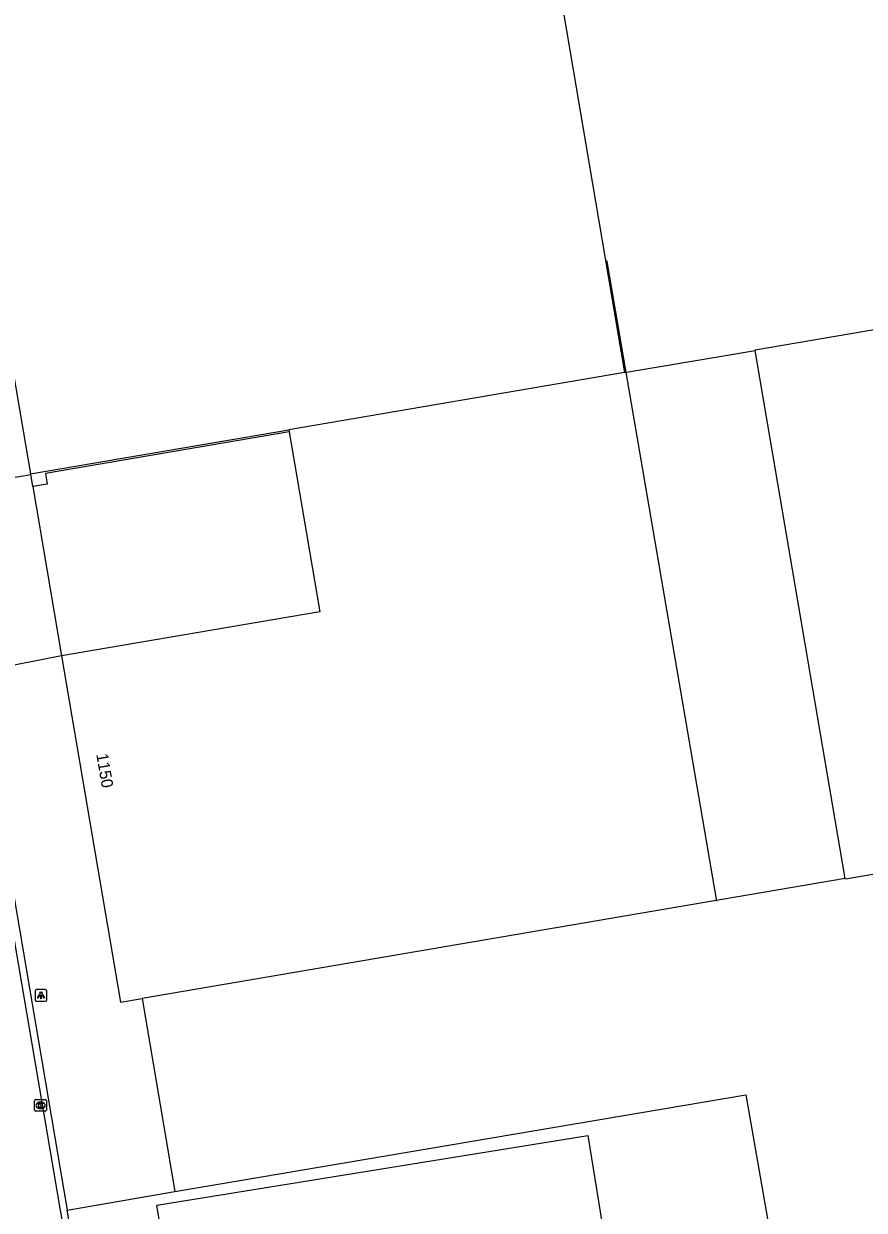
# Model space of a CAD drawing. Extents: x 154324 to 155743, y 382939 to 384183.
# Drawn here: x 154882.3 to 154954.2, y 383668.1 to 383769.7 of the extents above; entities that cross this region are included whole.
import ezdxf

# ---------------------------------------------------------------- set-up
doc = ezdxf.new("R2010")
doc.units = 0
for name, color, linetype in [('IMGEO_Grasland_agrarisch', 7, 'Continuous'), ('IMGEO_Hek', 7, 'Continuous'), ('IMGEO_Kolk', 7, 'Continuous'), ('IMGEO_Lichtpunt', 7, 'Continuous'), ('IMGEO_Muur', 7, 'Continuous'), ('IMGEO_Pand', 7, 'Continuous'), ('IMGEO_Pand_nummerreeks', 7, 'Continuous'), ('IMGEO_Pand_vergunning_verleend', 7, 'Continuous'), ('IMGEO_Rijbaan_lokaal_gesloten', 7, 'Continuous'), ('IMGEO_Rijbaan_lokaal_open', 7, 'Continuous'), ('IMGEO_Voetpad_open', 7, 'Continuous')]:
    doc.layers.add(name, color=color, linetype=linetype)

msp = doc.modelspace()

# ---------------------------------------------------------------- linework, layer by layer
at = {"layer": 'IMGEO_Grasland_agrarisch'}
msp.add_lwpolyline([(154895.23, 383669.68), (154944.1, 383677.97), (154949.34, 383647.91), (154982.71, 383457.88)], dxfattribs=at)
at = {"layer": 'IMGEO_Hek'}
msp.add_lwpolyline([(154932.18, 383749.38), (154932.22, 383749.12), (154941.57, 383694.55)], dxfattribs=at)
at = {"layer": 'IMGEO_Kolk'}
for p, q in [((154883.22, 383676.64), (154883.22, 383677.49)), ((154883.29, 383677.56), (154884.15, 383677.56)), ((154883.71, 383677.34), (154883.73, 383677.34)), ((154884.22, 383677.49), (154884.22, 383676.64)), ((154884.15, 383676.56), (154883.29, 383676.56)), ((154883.73, 383676.78), (154883.7, 383676.78))]:
    msp.add_line(p, q, dxfattribs=at)
for points in [[(154883.22, 383676.64), (154883.22, 383677.49)], [(154883.29, 383677.56), (154884.15, 383677.56)], [(154883.54, 383677.26), (154883.66, 383677.26), (154883.66, 383677.11), (154883.79, 383677.26), (154883.96, 383677.26), (154883.81, 383677.11), (154883.96, 383676.86), (154883.81, 383676.86), (154883.73, 383677.03), (154883.66, 383676.96), (154883.66, 383676.86), (154883.54, 383676.86), (154883.54, 383677.26)], [(154884.22, 383677.49), (154884.22, 383676.64)], [(154884.15, 383676.56), (154883.29, 383676.56)]]:
    msp.add_lwpolyline(points, dxfattribs=at)
for centre, start, end in [((154883.3, 383677.49), 91.552, 178.448), ((154883.3, 383677.49), 91.552, 178.448), ((154884.14, 383677.49), 1.552, 88.448), ((154884.14, 383677.49), 1.552, 88.448), ((154883.3, 383676.64), 181.552, 268.448), ((154883.3, 383676.64), 181.552, 268.448), ((154884.14, 383676.64), 271.552, 358.448), ((154884.14, 383676.64), 271.552, 358.448)]:
    msp.add_arc(centre, 0.0765, start, end, dxfattribs=at)
for centre, major_axis, ratio, start_param, end_param in [((154883.71, 383677.06), (-0.387, 0.002), 0.722429, 4.712389, 7.853982), ((154883.73, 383677.06), (-0.39, 0.002), 0.717154, 1.570796, 4.712389)]:
    msp.add_ellipse(centre, major_axis=major_axis, ratio=ratio, start_param=start_param, end_param=end_param, dxfattribs=at)
at = {"layer": 'IMGEO_Lichtpunt'}
for p, q in [((154884.16, 383686.97), (154883.36, 383686.97)), ((154884.16, 383686.97), (154883.36, 383686.97)), ((154883.26, 383686.87), (154883.26, 383686.07)), ((154883.26, 383686.87), (154883.26, 383686.07)), ((154883.36, 383685.97), (154884.16, 383685.97)), ((154883.36, 383685.97), (154884.16, 383685.97)), ((154884.26, 383686.07), (154884.26, 383686.87)), ((154884.26, 383686.07), (154884.26, 383686.87))]:
    msp.add_line(p, q, dxfattribs=at)
for points in [[(154883.64, 383686.54), (154883.67, 383686.51), (154883.49, 383686.25), (154883.45, 383686.27), (154883.64, 383686.54)], [(154883.74, 383686.49), (154883.78, 383686.49), (154883.78, 383686.17), (154883.74, 383686.17), (154883.74, 383686.49)], [(154883.85, 383686.51), (154883.89, 383686.54), (154884.07, 383686.27), (154884.03, 383686.25), (154883.85, 383686.51)]]:
    msp.add_lwpolyline(points, dxfattribs=at)
msp.add_circle((154883.76, 383686.67), 0.0994, dxfattribs=at)
for centre, start, end in [((154883.36, 383686.87), 90, 180), ((154883.36, 383686.87), 90, 180), ((154884.16, 383686.87), 0, 90), ((154884.16, 383686.87), 0, 90), ((154883.36, 383686.07), 180, 270), ((154883.36, 383686.07), 180, 270), ((154884.16, 383686.07), 270, 0), ((154884.16, 383686.07), 270, 360)]:
    msp.add_arc(centre, 0.0946, start, end, dxfattribs=at)
at = {"layer": 'IMGEO_Muur'}
for points in [[(154905.01, 383734.73), (154884.14, 383731.16), (154884.3, 383730.25), (154883.05, 383730.04)], [(154882.88, 383731.08), (154882.87, 383731.11)], [(154883.05, 383730.04), (154883.05, 383730.08), (154882.88, 383731.08)]]:
    msp.add_lwpolyline(points, dxfattribs=at)
at = {"layer": 'IMGEO_Pand'}
for points in [[(154925.99, 383785.24), (154933.72, 383739.79)], [(154875.11, 383776.48), (154882.87, 383731.11)], [(154944.89, 383741.69), (154944.88, 383741.74), (155001.21, 383751.34), (155008.93, 383706.03), (154952.61, 383696.43), (154952.6, 383696.48)], [(154933.72, 383739.79), (154944.89, 383741.69)], [(154952.6, 383696.48), (154944.89, 383741.69)], [(154933.72, 383739.79), (154904.98, 383734.88)], [(154882.87, 383731.11), (154904.98, 383734.88)], [(154905.01, 383734.73), (154907.63, 383719.32), (154885.53, 383715.54)], [(154904.98, 383734.88), (154905.01, 383734.73)], [(154885.53, 383715.54), (154890.57, 383685.9), (154892.43, 383686.21)], [(154952.6, 383696.48), (154892.43, 383686.21)]]:
    msp.add_lwpolyline(points, dxfattribs=at)
at = {"layer": 'IMGEO_Pand_vergunning_verleend'}
msp.add_lwpolyline([(154893.69, 383668.53), (154930.56, 383674.49), (154935.25, 383645.51), (154898.38, 383639.55), (154893.69, 383668.53)], dxfattribs=at)
at = {"layer": 'IMGEO_Rijbaan_lokaal_gesloten'}
msp.add_lwpolyline([(154859.21, 383821.78), (154860.59, 383813.67), (154872.99, 383740.87), (154875.26, 383727.61), (154875.73, 383724.69), (154937.89, 383359.92)], dxfattribs=at)
at = {"layer": 'IMGEO_Rijbaan_lokaal_open'}
for points in [[(154867.75, 383775.23), (154869.8, 383763.15), (154873.59, 383740.95), (154875.5, 383729.82), (154875.86, 383727.69), (154876.35, 383724.76), (154883, 383685.74), (154886, 383668.1)], [(154936.7, 383370.54), (154936.69, 383370.6), (154886, 383668.1)]]:
    msp.add_lwpolyline(points, dxfattribs=at)
at = {"layer": 'IMGEO_Voetpad_open'}
for points in [[(154885.53, 383715.54), (154879.55, 383714.38), (154876.86, 383730.05), (154882.88, 383731.08)], [(154883.05, 383730.04), (154885.53, 383715.54)], [(154892.43, 383686.21), (154895.23, 383669.68)], [(154886, 383668.1), (154895.23, 383669.68)]]:
    msp.add_lwpolyline(points, dxfattribs=at)

# ---------------------------------------------------------------- texts
at = {"layer": 'IMGEO_Pand_nummerreeks'}
msp.add_text('1150', height=1, rotation=279.6541, dxfattribs=at).set_placement((154888.49, 383707.11))

doc.saveas('drawing.dxf')
